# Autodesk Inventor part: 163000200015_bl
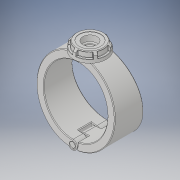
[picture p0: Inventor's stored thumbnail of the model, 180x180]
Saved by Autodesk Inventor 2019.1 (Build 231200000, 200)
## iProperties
Created: 2022-02
Part Number: 163000200015_bl
Material: Generic
Description: Plassadle Threaded 200x1 1/2''
Document SubType Name: Modeling
Designer: comp2
Density: 1 g/cm^3
Appearance: Default
Author: comp2
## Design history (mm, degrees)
derived "16300.ipt"
feature "Solid1::16300.ipt" dims "ScaleForDerivedMember" = 10
feature "Solid2::16300.ipt" dims "ScaleForDerivedMember" = 10
feature "Solid3::16300.ipt" dims "ScaleForDerivedMember" = 10
feature "Solid4::16300.ipt" dims "ScaleForDerivedMember" = 10
tag "TaggingFeature1"
body "Solid1"
body "Solid2"
body "Solid3"
body "Solid4"
other parameters: "d2" = 246 [user parameter], "d7" = 233.7 [user parameter], "d8" = 85 deg [user parameter], "d9" = 45 deg [user parameter], "d10" = 102 [user parameter], "d11" = 49 [user parameter], "d12" = 19.061 [user parameter], "d13" = 42.84 [user parameter], "d14" = 67.2675 [user parameter], "d42" = 4.6 [user parameter], "d49" = 4.92 [user parameter], "d50" = 115 [user parameter], "d51" = 0 [user parameter], "d52" = 32.2 [user parameter], "d53" = 135.3 [user parameter], "d54" = 40.25 [user parameter], "d55" = 0 [user parameter], "d56" = 23 [user parameter], "d57" = 23 [user parameter], "d59" = 0 [user parameter], "d60" = 115 [user parameter], "d61" = 0 [user parameter], "d62" = 40.25 [user parameter], "d63" = 0 [user parameter], "d65" = 0 [user parameter], "d67" = 0 [user parameter], "d69" = 0 [user parameter], "d70" = 1 [user parameter], "d71" = 110.4 [user parameter], "d72" = 0 [user parameter], "d73" = 2 [user parameter], "d78" = 86.7 [user parameter], "d79" = 5.1 [user parameter], "d80" = 60 deg [user parameter], "d81" = 5.1 [user parameter], "d84" = 0 [user parameter], "d85" = 1 [user parameter], "d87" = 360 deg [user parameter], "d122" = 49 [user parameter], "d124" = 42.80128 [user parameter], "d125" = 1.3615 [user parameter], "d127" = 272 [user parameter], "d129" = 44.845 [user parameter], "d130" = 38.11825 [user parameter], "d131" = 25.97 [user parameter], "d132" = 45 deg [user parameter], "d133" = 18.179 [user parameter], "d134" = 22.4225 [user parameter], "d136" = 0 [user parameter], "d138" = 0 [user parameter], "d1" = 25 [user parameter], "B" = 246 [user parameter], "L" = 115 [user parameter], "E_" = 54 [user parameter], "E1" = 102 [user parameter], "H1" = 272 [user parameter], "H2" = 49 [user parameter], "H3" = 78 [user parameter], "H_costum" = 49 [user parameter], "Rp" = 44.845 [user parameter], "d128" = 27.23 [user parameter]
